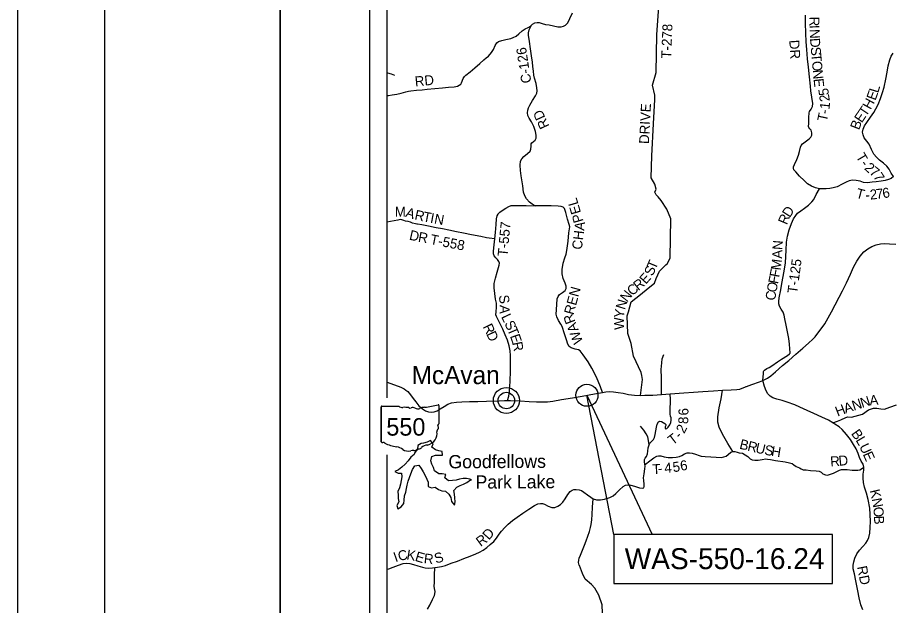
# Model space of a CAD drawing. Extents: x -84548 to 2262448, y -162180 to 525962.
# Drawn here: x 0 to 26368, y 86581 to 104330 of the extents above; entities that cross this region are included whole.
import ezdxf

# ---------------------------------------------------------------- set-up
doc = ezdxf.new("R2010")
doc.units = 0
for name, color, linetype in [('GM_X_Adjacent_County', 7, 'Continuous'), ('GM_X_Adjacent_County_Text', 7, 'Continuous'), ('GM_X_County', 7, 'Continuous'), ('GM_X_County_Road', 7, 'Continuous'), ('GM_X_Interchange_Ramps', 7, 'Continuous'), ('GM_X_Major_Lake_Text', 7, 'Continuous'), ('GM_X_Major_River', 7, 'Continuous'), ('GM_X_Minor_Lake', 7, 'Continuous'), ('GM_X_Minor_River_Text', 7, 'Continuous'), ('GM_X_Rail_Line', 7, 'Continuous'), ('GM_X_Section', 7, 'Continuous'), ('GM_X_State_Route', 7, 'Continuous'), ('GM_X_Township', 7, 'Continuous'), ('GM_X_Township_Road', 7, 'Continuous'), ('GM_X_Township_Road_Text', 7, 'Continuous'), ('GM_X_Township_ROW', 7, 'Continuous'), ('GM_X_Unincorporated_Text', 7, 'Continuous')]:
    doc.layers.add(name, color=color, linetype=linetype)

msp = doc.modelspace()

# ---------------------------------------------------------------- linework, layer by layer
at = {"layer": 'GM_X_Adjacent_County'}
for points in [[(2640, 113520), (7920, 113520), (7920, 2640), (2640, 2640)], [(7920, 113520), (176880, 113520), (176880, 2640), (7920, 2640)]]:
    msp.add_lwpolyline(points, close=True, dxfattribs=at)
at = {"layer": 'GM_X_Adjacent_County_Text'}
msp.add_circle((17178, 92929), 334, dxfattribs=at)
at = {"layer": 'GM_X_County'}
for p, q in [((10619, 110849), (10619, 73889)), ((11147, 110321), (11147, 92849)), ((11147, 91128), (11147, 74417))]:
    msp.add_line(p, q, dxfattribs=at)
at = {"layer": 'GM_X_Interchange_Ramps'}
for points in [[(13675, 90384), (13651, 90396), (13549, 90414), (13444, 90418), (13338, 90400), (13237, 90370), (13127, 90358), (13000, 90348), (12893, 90440), (12918, 90541), (12817, 90561), (12713, 90555), (12582, 90649), (12550, 90749), (12503, 90851), (12469, 90952), (12499, 91080), (12614, 91118), (12719, 91118), (12819, 91124), (12813, 91226), (12713, 91254), (12612, 91278), (12501, 91359), (12536, 91461), (12461, 91561), (12357, 91517), (12252, 91477)], [(12252, 91477), (12180, 91467), (12079, 91407), (12067, 91300), (11991, 91198)], [(11991, 91198), (11963, 91142), (11862, 91056), (11782, 90948), (11699, 90843), (11595, 90759), (11490, 90681), (11384, 90627), (11484, 90581), (11589, 90573), (11591, 90462), (11573, 90352), (11551, 90248), (11523, 90134), (11478, 90023), (11488, 89917), (11486, 89813), (11504, 89709), (11440, 89598), (11478, 89496), (11579, 89560), (11659, 89661), (11663, 89765), (11677, 89893), (11711, 90005), (11732, 90112), (11758, 90216), (11788, 90332), (11830, 90444), (11868, 90555), (11916, 90687), (11991, 90799), (12109, 90819), (12176, 90719), (12236, 90613), (12298, 90509), (12353, 90400), (12393, 90300), (12387, 90170), (12491, 90134), (12600, 90150), (12703, 90084), (12803, 90044), (12910, 90038), (13018, 89947), (13070, 89841), (13095, 89717), (13181, 89611), (13203, 89711), (13199, 89835), (13185, 89943), (13163, 90052), (13251, 90158), (13352, 90200), (13460, 90246), (13561, 90292), (13667, 90376)], [(13667, 90376), (13692, 90372)], [(13692, 90372), (13675, 90384)]]:
    msp.add_lwpolyline(points, dxfattribs=at)
at = {"layer": 'GM_X_Major_Lake_Text'}
for points in [[(22481, 93370), (22530, 93391), (22629, 93439), (22731, 93518), (22872, 93637), (23083, 93823), (23268, 93972), (23484, 94164), (23695, 94350), (23868, 94497), (23999, 94616), (24068, 94690), (24146, 94801), (24245, 94928), (24356, 95085), (24460, 95264), (24557, 95447), (24672, 95658), (24792, 95889), (24887, 96078), (25007, 96323), (25127, 96578), (25226, 96793), (25325, 96976), (25422, 97123), (25529, 97252), (25650, 97351), (25772, 97418), (25907, 97467), (26033, 97496), (26147, 97504), (26303, 97501), (26503, 97487)], [(21987, 93188), (21992, 93190), (22151, 93252), (22386, 93331), (22481, 93370)], [(11147, 93326), (11155, 93323), (11564, 93177), (11664, 93122), (11720, 93084), (11775, 93046), (11857, 92938)], [(14527, 92764), (14695, 92770), (14787, 92772), (14869, 92773), (15163, 92755), (15433, 92743), (15655, 92732), (15849, 92727), (15993, 92734), (16152, 92753), (16408, 92795), (16747, 92851), (17031, 92901), (17404, 92972), (17654, 93015), (17754, 93032), (17873, 93041), (17979, 93033), (18121, 93014), (18269, 92987), (18436, 92954), (18612, 92927), (18800, 92923), (18927, 92927), (19169, 92935), (19427, 92951), (19690, 92973), (20100, 93000), (20394, 93018), (20677, 93040), (20993, 93062), (21270, 93083), (21530, 93096), (21706, 93101), (21794, 93115), (21968, 93181), (21987, 93188)], [(11857, 92938), (11941, 92827), (12016, 92733), (12112, 92611), (12215, 92514), (12311, 92454), (12399, 92427), (12485, 92421), (12567, 92432), (12657, 92461), (12756, 92517), (12870, 92590), (12981, 92661), (13093, 92698), (13247, 92721), (13403, 92734), (13634, 92737), (13884, 92741), (14152, 92751), (14527, 92764)]]:
    msp.add_lwpolyline(points, dxfattribs=at)
at = {"layer": 'GM_X_Major_River'}
for radius in [393, 249]:
    msp.add_circle((14749, 92769), radius, dxfattribs=at)
at = {"layer": 'GM_X_Minor_Lake'}
for points in [[(19226, 101853), (19232, 101981), (19156, 102285), (19270, 102666), (19289, 103806), (19373, 104953)], [(24193, 99161), (24077, 99187), (23950, 99238), (23838, 99310), (23734, 99406), (23595, 99545), (23478, 99667), (23424, 99733), (23408, 99779), (23412, 99825), (23437, 99897), (23508, 100048), (23562, 100176), (23591, 100287), (23622, 100419), (23644, 100471), (23680, 100519), (23799, 100606), (23885, 100666), (23937, 100717), (23962, 100775), (23966, 100845), (23940, 100925), (23901, 100973), (23875, 101007), (23865, 101041), (23870, 101127), (23876, 101308), (23881, 101450), (23891, 101492), (23948, 101566), (23986, 101645), (23993, 101729), (23968, 101925), (23939, 102115), (23921, 102255), (23891, 102536), (23864, 102830), (23838, 103083), (23815, 103365), (23798, 103599), (23788, 103860), (23777, 104160), (23776, 104395)], [(11147, 101980), (11196, 101980), (11306, 101992), (11447, 102017), (11576, 102047), (11714, 102084), (11793, 102110), (11867, 102119), (12034, 102135), (12204, 102146), (12364, 102165), (12589, 102184), (12823, 102209), (13006, 102222), (13178, 102240), (13271, 102260), (13329, 102287), (13374, 102318), (13399, 102360), (13448, 102493), (13481, 102548), (13523, 102585), (13656, 102688), (13798, 102807), (13951, 102940), (14067, 103053), (14140, 103110), (14206, 103166), (14300, 103270), (14358, 103363), (14406, 103482), (14462, 103565), (14511, 103605), (14615, 103635), (14736, 103667), (14881, 103700), (14959, 103724), (15044, 103771), (15126, 103839), (15228, 103927), (15315, 103987), (15404, 104031), (15494, 104081)], [(26425, 99528), (26355, 99636), (26298, 99750), (26230, 99842), (26131, 99929), (26009, 100025), (25911, 100113), (25838, 100204), (25767, 100342), (25693, 100506), (25626, 100598), (25546, 100698), (25511, 100784), (25497, 100872), (25514, 100958), (25554, 101055), (25627, 101165), (25736, 101322), (25832, 101465), (25899, 101571), (25964, 101706), (26033, 101880), (26094, 102061), (26143, 102227), (26198, 102464), (26237, 102683), (26266, 102875), (26313, 103050), (26362, 103160), (26416, 103252)], [(19188, 101124), (19226, 101851), (19226, 101853)], [(19564, 96861), (19613, 96905), (19689, 97076), (19708, 98255), (19594, 98540), (19423, 98806), (19327, 98920), (19270, 98977), (19232, 99054), (19270, 99149), (19232, 99301), (19118, 99491), (19137, 100156), (19188, 101123), (19188, 101124)], [(26425, 99528), (26354, 99473), (26274, 99435), (26172, 99405), (26060, 99388), (25906, 99373), (25785, 99361), (25641, 99344), (25521, 99353), (25423, 99387), (25301, 99413), (25187, 99418), (25087, 99404), (24995, 99363), (24875, 99299), (24726, 99220), (24612, 99185), (24504, 99165), (24400, 99160), (24293, 99158), (24193, 99161)], [(23249, 94741), (23248, 94742), (23230, 94845), (23189, 95048), (23154, 95232), (23125, 95346), (23097, 95432), (23038, 95526), (22988, 95616), (22972, 95684), (22965, 95758), (22981, 95868), (23027, 96111), (23064, 96301), (23101, 96512), (23144, 96732), (23171, 96929), (23184, 97119), (23187, 97305), (23204, 97552), (23233, 97732), (23278, 97917), (23353, 98116), (23414, 98250), (23481, 98355), (23535, 98423), (23630, 98492), (23740, 98570), (23863, 98667), (23967, 98766), (24026, 98836), (24100, 98984), (24193, 99161)], [(14500, 98398), (14503, 98406), (14550, 98459), (14627, 98509), (14734, 98577), (14821, 98627), (14896, 98652), (14966, 98658), (15124, 98655), (15346, 98651), (15614, 98645)], [(14787, 92772), (14820, 92897), (14847, 93048), (14858, 93179), (14862, 93361), (14871, 93648), (14877, 93928), (14875, 94124), (14862, 94272), (14835, 94418), (14783, 94587), (14714, 94756), (14639, 94923), (14547, 95105), (14453, 95302), (14432, 95358), (14440, 95442), (14453, 95590), (14447, 95708), (14424, 95830), (14397, 95996), (14377, 96170), (14381, 96298), (14417, 96465), (14469, 96644), (14533, 96858), (14540, 96910), (14525, 96966), (14486, 97027), (14431, 97078), (14382, 97133), (14360, 97193), (14363, 97275), (14383, 97464), (14401, 97645), (14402, 97654), (14419, 97843), (14440, 98080), (14455, 98253), (14471, 98341), (14499, 98397), (14500, 98398)], [(12072, 98090), (12043, 98095), (12007, 98102), (11922, 98124), (11856, 98153), (11785, 98177), (11705, 98186), (11651, 98203), (11599, 98222), (11546, 98231), (11477, 98215), (11254, 98169), (11147, 98155)], [(14402, 97654), (14225, 97667), (14147, 97678), (13974, 97716), (13695, 97773), (13460, 97820), (13243, 97864), (13010, 97911), (12820, 97948), (12631, 97984), (12402, 98027), (12195, 98067), (12072, 98090)], [(18429, 95447), (18429, 95448), (18510, 95746), (18795, 95974), (19023, 96164), (19214, 96316), (19271, 96449), (19366, 96677), (19563, 96860), (19564, 96861)], [(18800, 92923), (18853, 93407), (18840, 93527), (18815, 93617), (18586, 94111), (18510, 94491), (18415, 94795), (18396, 95328), (18429, 95447)], [(22757, 93817), (22927, 93934), (23052, 94013), (23228, 94132), (23295, 94179), (23311, 94194), (23315, 94213), (23305, 94325), (23288, 94467), (23267, 94639), (23249, 94741)], [(22481, 93370), (22503, 93580), (22509, 93646), (22518, 93667), (22532, 93684), (22608, 93733), (22674, 93765), (22756, 93816), (22757, 93817)], [(18930, 90844), (18913, 90916), (18921, 90986), (18938, 91028), (18975, 91083), (19004, 91158), (19014, 91236), (19028, 91345), (19054, 91436), (19081, 91486), (19130, 91529), (19185, 91590), (19213, 91653), (19235, 91745), (19255, 91854), (19275, 91964), (19299, 92055), (19342, 92124), (19379, 92145), (19429, 92132), (19529, 92076), (19555, 92042), (19556, 92012), (19537, 91974), (19535, 91938), (19554, 91918), (19586, 91925), (19635, 91968), (19679, 92031), (19714, 92105), (19720, 92176), (19719, 92242), (19698, 92295), (19687, 92353), (19690, 92468), (19692, 92578), (19702, 92674), (19698, 92796), (19690, 92973)], [(24597, 92097), (24741, 92143), (24844, 92185), (24987, 92260), (25055, 92272), (25159, 92268), (25488, 92359), (25676, 92489), (25825, 92539), (25929, 92535), (26046, 92519), (26158, 92506), (26314, 92565), (26514, 92643)], [(19054, 91436), (19039, 91559), (19017, 91669), (18967, 91768), (18897, 91875), (18797, 91991)], [(18931, 90844), (18943, 90853), (19080, 90951), (19198, 91037), (19285, 91091), (19341, 91102), (19409, 91096), (19509, 91070), (19629, 91054), (19763, 91049), (19867, 91059), (19971, 91083), (20042, 91108), (20127, 91158), (20202, 91186), (20272, 91187), (20355, 91177), (20455, 91147), (20562, 91107), (20630, 91092), (20746, 91082), (20914, 91072), (21075, 91059), (21227, 91054), (21306, 91067), (21380, 91091), (21437, 91140), (21519, 91210), (21583, 91231), (21591, 91233), (21645, 91230), (21709, 91208), (21769, 91195), (21870, 91175), (21951, 91134), (22030, 91076), (22105, 91013), (22164, 90978), (22248, 90966), (22348, 90968), (22463, 90986), (22573, 91005), (22631, 91002), (22721, 90986), (22870, 90960), (23159, 90914), (23295, 90889), (23367, 90868), (23420, 90827), (23487, 90779), (23538, 90755), (23594, 90735), (23639, 90707), (23701, 90681), (23793, 90672), (23927, 90657), (24098, 90651), (24188, 90638), (24246, 90607), (24301, 90556), (24372, 90524), (24434, 90519), (24524, 90543), (24615, 90577), (24714, 90627), (24801, 90667), (24857, 90684), (24930, 90689), (25034, 90685), (25183, 90670), (25287, 90662), (25351, 90664), (25416, 90679), (25462, 90710), (25528, 90759)], [(11147, 87678), (11204, 87691), (11337, 87737), (11498, 87799), (11635, 87847), (11735, 87861), (11841, 87850), (11945, 87824), (12076, 87780), (12219, 87739), (12301, 87717), (12413, 87711), (12521, 87717), (12586, 87725), (12605, 87728), (12669, 87736), (12796, 87755), (12912, 87785), (13086, 87855), (13273, 87924), (13463, 88000), (13657, 88072), (13832, 88138), (13941, 88188), (14047, 88254), (14158, 88331), (14264, 88419), (14368, 88515), (14450, 88619), (14531, 88733), (14601, 88824), (14699, 88933), (14807, 89035), (14929, 89147), (15071, 89246), (15244, 89368), (15431, 89490), (15601, 89602), (15700, 89648), (15776, 89661), (15836, 89660), (15900, 89636), (16009, 89582), (16124, 89540), (16208, 89536), (16301, 89576), (16382, 89629), (16453, 89703), (16521, 89802), (16600, 89932), (16670, 90022), (16731, 90065), (16789, 90086), (16853, 90087), (16947, 90077), (17015, 90056), (17086, 90006), (17192, 89926), (17295, 89850), (17366, 89801), (17465, 89773), (17591, 89771), (17714, 89794), (17871, 89845), (17972, 89889), (18049, 89961), (18160, 90071), (18272, 90176), (18341, 90213), (18411, 90224), (18503, 90210), (18618, 90179), (18769, 90135), (18853, 90123), (18891, 90134), (18910, 90176), (18908, 90246), (18894, 90358), (18890, 90434), (18904, 90561), (18929, 90704), (18941, 90786), (18930, 90844), (18931, 90844)], [(16950, 87801), (16930, 87879), (16932, 87949), (16945, 88012), (16981, 88101), (17042, 88248), (17109, 88402), (17154, 88533), (17203, 88670), (17252, 88817), (17286, 88938), (17308, 89031), (17325, 89165), (17342, 89326), (17351, 89552), (17366, 89801)], [(12372, 86475), (12440, 86596), (12523, 86759), (12576, 86881), (12593, 86937), (12596, 87001), (12584, 87093), (12574, 87163), (12578, 87281), (12584, 87494), (12586, 87725)], [(17662, 86092), (17640, 86603), (17542, 86897), (17422, 87104), (17314, 87212), (17129, 87375), (17042, 87549), (16954, 87790), (16950, 87801)]]:
    msp.add_lwpolyline(points, dxfattribs=at)
at = {"layer": 'GM_X_Minor_River_Text'}
for points in [[(15197, 99548), (15197, 99549), (15171, 99708), (15164, 99871), (15174, 99989), (15211, 100063), (15277, 100132), (15386, 100222), (15470, 100295), (15491, 100353), (15493, 100447), (15499, 100515), (15522, 100551), (15572, 100586), (15618, 100624), (15652, 100690), (15647, 100774), (15627, 100884), (15578, 101038), (15511, 101184), (15439, 101288), (15396, 101370), (15386, 101450), (15393, 101532), (15413, 101607), (15455, 101685), (15540, 101822), (15625, 101964), (15665, 102049), (15676, 102117), (15672, 102209), (15643, 102341), (15594, 102497), (15578, 102593), (15563, 102709), (15552, 102851), (15534, 102984), (15503, 103172), (15474, 103388), (15445, 103606), (15416, 103801), (15415, 103863), (15441, 103957), (15494, 104081), (15496, 104085), (15534, 104128), (15610, 104172), (15673, 104182), (15735, 104175), (15830, 104151), (15932, 104123), (16040, 104104), (16168, 104076), (16298, 104051), (16406, 104045), (16476, 104064), (16535, 104098), (16599, 104166), (16666, 104301), (16739, 104472)], [(16259, 95521), (16270, 95668), (16283, 95839), (16308, 95905), (16356, 95967), (16440, 96030), (16519, 96092), (16555, 96152), (16549, 96220), (16520, 96308), (16463, 96450), (16435, 96591), (16430, 96725), (16459, 96919), (16512, 97080), (16557, 97190), (16575, 97298), (16609, 97583), (16636, 97828), (16659, 98010), (16647, 98084), (16598, 98246), (16541, 98446), (16506, 98564), (16460, 98604), (16400, 98626), (16310, 98640), (16100, 98641), (15872, 98644), (15614, 98645), (15532, 98694), (15444, 98756), (15353, 98852), (15301, 98950), (15270, 99060), (15241, 99252), (15206, 99492), (15197, 99548)], [(17654, 93015), (17586, 93182), (17464, 93474), (17331, 93744), (17220, 93937), (17067, 94151), (16976, 94273), (16922, 94301), (16826, 94324), (16706, 94362), (16642, 94402), (16602, 94470), (16561, 94602), (16500, 94786), (16429, 95002), (16397, 95074), (16324, 95186), (16274, 95292), (16255, 95374), (16258, 95506), (16259, 95521), (16259, 95521)], [(25505, 86453), (25440, 86607), (25397, 86815), (25348, 87029), (25294, 87330), (25253, 87536), (25214, 87688), (25212, 87798), (25227, 87904), (25259, 88009), (25320, 88139), (25403, 88254), (25507, 88368), (25592, 88463), (25648, 88545), (25685, 88630), (25712, 88764), (25728, 88932), (25733, 89117), (25725, 89333), (25713, 89515), (25659, 89786), (25614, 89972), (25557, 90152), (25525, 90290), (25508, 90428), (25517, 90550), (25533, 90668), (25528, 90759), (25508, 90843), (25455, 90943), (25401, 91049), (25362, 91165), (25301, 91307), (25225, 91442), (25132, 91588), (25009, 91742), (24880, 91896), (24790, 91975), (24662, 92059), (24597, 92097), (24463, 92174), (24265, 92268), (24020, 92381), (23822, 92468), (23598, 92573), (23453, 92635), (23217, 92720), (23067, 92769), (22907, 92808), (22783, 92848), (22704, 92902), (22640, 92966), (22590, 93061), (22535, 93191), (22481, 93370)]]:
    msp.add_lwpolyline(points, dxfattribs=at)
at = {"layer": 'GM_X_Rail_Line'}
for p, q in [((10975, 92577), (10975, 91521)), ((10975, 91521), (10975, 92577)), ((10975, 91521), (10975, 92577)), ((10992, 92595), (11501, 92595)), ((12715, 92622), (12715, 92069)), ((12715, 92069), (12715, 92069))]:
    msp.add_line(p, q, dxfattribs=at)
for centre, major_axis, start_param, end_param in [((10994, 92580), (20.2, 0), 1.712693, 3.28349), ((11623, 92718), (196, 0), 4.042523, 4.731795), ((11687, 92002), (702, 0), 1.404758, 1.657858), ((11847, 92585), (56.4, 0), 3.836095, 5.185415), ((11930, 92463), (117, 0), 0.950623, 2.079405), ((12330, 92273), (371, 0), 1.699011, 2.107814), ((12095, 94036), (1845, 0), 4.814394, 5.042369), ((12695, 92624), (19.4, 0), 6.141152, 7.989035), ((12081, 92630), (141, 0), 4.081561, 5.145723), ((12710, 92028), (30, 0), 1.883978, 3.671073), ((12694, 92067), (20.7, 0), 5.05454, 6.418171), ((12198, 91767), (462, 0), 5.101752, 6.440018), ((12784, 91838), (131, 0), 2.387724, 3.262537), ((12519, 91958), (180, 0), 5.934695, 6.695948), ((10995, 91518), (20.3, 0), 3.00124, 4.508301), ((10998, 91626), (155, 0), 4.665946, 4.897461), ((11029, 91460), (56, 0), 0.519207, 1.627899), ((11736, 92409), (1333, 0), 4.195997, 4.488961), ((11339, 91046), (417, 0), 0.823519, 1.323587), ((11790, 91454), (265, 0), 4.026481, 4.996735), ((11943, 91089), (217, 0), 1.495662, 1.94098), ((11962, 91375), (141, 0), 4.691044, 5.507374), ((12089, 91273), (39.7, 0), 1.147584, 2.315152), ((12073, 91418), (149, 0), 4.937069, 5.64225), ((12393, 91224), (253, 0), 1.647645, 2.488434)]:
    msp.add_ellipse(centre, major_axis=major_axis, ratio=0.8, start_param=start_param, end_param=end_param, dxfattribs=at)
at = {"layer": 'GM_X_Section'}
for points in [[(17992, 88722), (17178, 92929), (19144, 88722)], [(17992, 87244), (24592, 87244), (24592, 88722), (17992, 88722)]]:
    msp.add_lwpolyline(points, close=True, dxfattribs=at)
at = {"layer": 'GM_X_State_Route'}
msp.add_lwpolyline([(11387, 102583), (11287, 102619), (11172, 102653), (11147, 102664)], dxfattribs=at)
at = {"layer": 'GM_X_Township'}
msp.add_lwpolyline([(0, 0), (179520, 0), (179520, 116160), (0, 116160)], close=True, dxfattribs=at)
at = {"layer": 'GM_X_Township_Road_Text'}
msp.add_lwpolyline([(21583, 91231), (21429, 91467), (21271, 91757), (21166, 91961), (21124, 92112), (21130, 92276), (21170, 92551), (21224, 92823), (21270, 93083)], dxfattribs=at)
at = {"layer": 'GM_X_Township_ROW'}
msp.add_lwpolyline([(19427, 92951), (19427, 93222), (19428, 93458), (19423, 93704), (19437, 93903), (19453, 94029), (19502, 94155)], dxfattribs=at)

# ---------------------------------------------------------------- texts
at = {"layer": 'GM_X_Adjacent_County_Text'}
msp.add_text('McAvan', height=550, rotation=0, dxfattribs=at).set_placement((11891, 93263))
at = {"layer": 'GM_X_County'}
msp.add_text('WAS-550-16.24', height=633.6, dxfattribs=at).set_placement((18319, 87679))
at = {"layer": 'GM_X_County_Road'}
for s, rotation, p in [('C-126', 98.8366, (15506, 102368)), ('RD', 114.9422, (16053, 101051)), ('PEL', 106.3899, (17080, 98182)), ('CHA', 83.0464, (17024, 97310)), ('REN', 74.6808, (16772, 95339)), ('WAR', 110.9772, (17068, 94543)), ('B', 305.7602, (25137, 91768)), ('L', 300.5231, (25277, 91574)), ('U', 294.8103, (25387, 91388)), ('E', 293.7149, (25497, 91150)), ('K', 283.3922, (25711, 90053)), ('N', 280.6098, (25771, 89800)), ('O', 274.2624, (25819, 89550)), ('B', 272.155, (25838, 89289)), ('RD', 281.3097, (25326, 87748))]:
    msp.add_text(s, height=300, rotation=rotation, dxfattribs=at).set_placement(p)
at = {"layer": 'GM_X_Rail_Line'}
msp.add_text('550', height=528, dxfattribs=at).set_placement((11128, 91709))
at = {"layer": 'GM_X_Township_Road'}
for s, rotation, p in [('R', 270.7203, (23890, 104352)), ('T-278', 87.6374, (19718, 103085)), ('I', 271.8675, (23893, 104099)), ('N', 272.3608, (23897, 103973)), ('DR', 273.9488, (23282, 103644)), ('D', 274.0728, (23908, 103700)), ('S', 275.1649, (23928, 103430)), ('T', 275.2434, (23946, 103228)), ('O', 275.2443, (23966, 103004)), ('RD', 5.2796, (12000, 102248)), ('N', 275.248, (23991, 102742)), ('E', 275.8027, (24015, 102476)), ('5', 97.9932, (24483, 101994)), ('E', 70.3871, (25884, 101808)), ('L', 73.2395, (25965, 102034)), ('2', 98.6593, (24511, 101812)), ('H', 61.2751, (25736, 101530)), ('DRIVE', 87.0767, (19050, 100506)), ('1', 84.0438, (24494, 101545)), ('-', 78.3918, (24464, 101393)), ('T', 56.2811, (25597, 101319)), ('T', 77.8142, (24416, 101170)), ('E', 55.5016, (25468, 101130)), ('B', 68.9618, (25388, 100917)), ('T', 300.3493, (25282, 100133)), ('-', 305.9949, (25413, 99912)), ('2', 317.2467, (25528, 99764)), ('7', 320.944, (25679, 99625)), ('7', 302.365, (25806, 99528)), ('T', 344.9721, (25272, 98893)), ('2', 5.7182, (25729, 98831)), ('7', 6.2125, (25915, 98850)), ('6', 9.2907, (26117, 98872)), ('-', 2.5878, (25588, 98824)), ('D', 57.1798, (23298, 98270)), ('M', 0.2333, (11384, 98315)), ('A', 342.9532, (11686, 98320)), ('R', 347.4548, (11963, 98236)), ('T', 349.2826, (12214, 98180)), ('I', 349.2672, (12435, 98138)), ('N', 349.2655, (12556, 98115)), ('R', 67.186, (23209, 98055)), ('T-557', 84.5229, (14781, 97109)), ('D', 347.2175, (11800, 97628)), ('R', 349.8245, (12071, 97567)), ('T-558', 348.8534, (12431, 97496)), ('N', 85.7668, (23072, 97306)), ('A', 88.6056, (23066, 97046)), ('T', 67.2184, (19251, 96702)), ('S', 64.5291, (19158, 96506)), ('M', 82.3671, (23020, 96688)), ('T-125', 82.3666, (23521, 95986)), ('E', 47.9617, (18955, 96261)), ('F', 79.0381, (22941, 96272)), ('F', 79.1899, (22979, 96471)), ('C', 39.7836, (18541, 95913)), ('R', 39.4593, (18730, 96070)), ('O', 79.1305, (22891, 96013)), ('N', 51.6736, (18389, 95718)), ('C', 81.6337, (22856, 95772)), ('S', 277.8647, (14518, 95938)), ('N', 73.0783, (18326, 95491)), ('A', 268.5792, (14552, 95654)), ('Y', 82.0479, (18292, 95242)), ('L', 295.2472, (14585, 95301)), ('W', 91.555, (18302, 94907)), ('R', 296.1112, (14029, 94998)), ('S', 295.7986, (14682, 95095)), ('T', 293.0104, (14769, 94916)), ('D', 294.9431, (14136, 94778)), ('E', 288.9743, (14854, 94715)), ('R', 281.561, (14925, 94513)), ('N', 18.3295, (25231, 92461)), ('N', 17.863, (25481, 92544)), ('A', 5.0244, (25715, 92621)), ('H', 21.0323, (24739, 92282)), ('A', 18.8197, (24982, 92376)), ('6', 91.8381, (20246, 92322)), ('2', 63.2385, (20116, 91753)), ('8', 88.3779, (20234, 92056)), ('T', 37.3053, (19764, 91410)), ('-', 49.436, (19992, 91594)), ('B', 346.4579, (21763, 91319)), ('R', 346.456, (22003, 91261)), ('U', 346.8998, (22245, 91203)), ('S', 349.1221, (22515, 91141)), ('H', 351.1425, (22725, 91100)), ('6', 7.4922, (20010, 90649)), ('R', 4.127, (24529, 90777)), ('D', 6.1461, (24786, 90796)), ('T', 3.6667, (19164, 90541)), ('-', 3.8952, (19328, 90568)), ('4', 4.5891, (19527, 90583)), ('5', 6.2983, (19782, 90608)), ('D', 48.9937, (14222, 88540)), ('R', 36.4655, (13972, 88345)), ('I', 19.3088, (11404, 87885)), ('C', 12.0991, (11511, 87923)), ('K', 350.9191, (11723, 87974)), ('E', 342.9408, (11973, 87935)), ('R', 353.8481, (12248, 87857)), ('S', 17.5896, (12627, 87844))]:
    msp.add_text(s, height=300, rotation=rotation, dxfattribs=at).set_placement(p)
at = {"layer": 'GM_X_Unincorporated_Text'}
for s, p in [('Goodfellows', (13001, 90721)), ('Park Lake', (13817, 90109))]:
    msp.add_text(s, height=400, rotation=0.3165, dxfattribs=at).set_placement(p)

doc.saveas('drawing.dxf')
